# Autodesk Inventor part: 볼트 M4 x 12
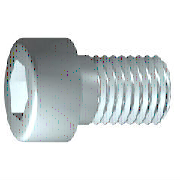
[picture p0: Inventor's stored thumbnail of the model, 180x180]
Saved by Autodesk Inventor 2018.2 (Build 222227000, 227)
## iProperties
IsCustomPart: 0
Created: 2012-02
Part Number: 볼트 M4 x 12
Material: 스테인리스강
Description: 6각 소켓 머리 캡 나사
Document SubType Name: Modeling
Standard: ISO 4762
Designer: mduedu
Standard Revision: Fourth edition 2004-03-01
Standards Organization: ISO
Language: ko-KR
Size Designation: M4 x 8
Categories: <MemberInstance><Categories><Category DisplayName="조임쇠" InternalName="e4da775c-781d-43d5-af7c-5136215cf5a6" Mnemonic="FSTN"><Category DisplayName="볼트" InternalN
Density: 8.08 g/cm^3
Mass: 2.2972 g
Surface Area: 3.30853 cm^2
Volume: 0.284306 cm^3
Appearance: 반광택
Author: mduedu
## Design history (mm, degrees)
sketch "스케치1"
  geometry: L1 (-1, 0)-(12, 0); L2 (12, 0)-(12, 2); L3 (12, 2)-(1.75, 2); L4 (1.75, 2)-(1.32, 2); L5 (1.32, 2)-(0, 2); L6 (0, 2)-(0, 3.5); L7 (0, 3.5)-(-4, 3.5); L8 (-4, 3.5)-(-4, 1.732); L9 (-4, 1.732)-(-2, 1.732); L10 (-2, 1.732)-(-1, 0); L11 (-7.2, 0)-(15.2, 0) reference; L12 (0, -0.7)-(0, 4.2) reference; L13 (1.75, 2)-(0, 2)
  constraints: 22 end point, 6 parallel, 2 collinear, 2 perpendicular, 1 horizontal, 1 point on line
  dimensions: "d1" = 10.25 distance from line of L3.end L2 (= GEL); "d2" = 0.42952 distance of L4.end L3.end (computed from GAL); "d3" = 4 distance between parallel lines of L8 L6 (= KOH); "d4" = 2 distance of L8.end L9.end (= INTI); "d5" = 60 deg angle of L10 L1; "d6" = 4 diameter of L3 L1 (= GD); "d7" = 4 diameter of L5 L1 (= BDM); "d8" = 3.4641 diameter of L9 L1 (= 1.1547 x SW); "d9" = 7 diameter of L7 L1 (= KOD); "d26" = 12 distance between parallel lines of L12 L2 (= NLG)
revolve "본체" sketch "스케치1" stored, may be unused: angle "d10" = 90 deg
sketch "스케치2"
  geometry: L1 (0, -4.9)-(0, 4.9) reference; L2 (-4.9, 0)-(4.9, 0) reference; L3 (1.732, 0)-(0.866, -1.5); L4 (0.866, -1.5)-(-0.866, -1.5); L5 (-0.866, -1.5)-(-1.732, 0); L6 (-1.732, 0)-(-0.866, 1.5); L7 (-0.866, 1.5)-(0.866, 1.5); L8 (0.866, 1.5)-(1.732, 0); 2 further points
  constraints: 12 end point, 1 coincident, 1 horizontal alignment, 1 point on line, 12 other
extrude "슬롯" join sketch "스케치2" stored distance "d11" = 10; taper "d12" = 0 deg
workplane "Work Plane1"
fillet "Fillet2" dims "d30" = 0.1 (= R)
body "Solid1"
fillet "모깎기1" dims "d17" = 0.4 (= RR)
feature "스레드" dims "d13" = 10.25 (= GEL), "d14" = 0
chamfer "모따기1" distance "d15" = 0.42941 (= -0.5 x SPD + 0.5 x GD); stored, may be unused: second distance "d16" = 0.42941 (= GUL), angle "d27" = 45 deg
other parameters: "GD" = 4 [user parameter; used in 2 equation terms], "NLG" = 12 [user parameter; used in 1 equation term], "GEL" = 10.25 [user parameter; used in 2 equation terms], "KOD" = 7 [user parameter; used in 1 equation term], "KOH" = 4 [user parameter; used in 1 equation term], "INTI" = 2 [user parameter; used in 1 equation term], "GAL" = 0.42941 (= 0.61345 x PTC) [user parameter; used in 1 equation term], "GUL" = 0.42941 (= 0.61345 x PTC) [user parameter; used in 1 equation term], "BDM" = 4 (= NND) [user parameter; used in 1 equation term], "SW" = 3 [user parameter; used in 2 equation terms], "RR" = 0.4 [user parameter; used in 1 equation term], "SPD" = 3.14117 (= NND - 1.2269 x PTC) [user parameter; used in 1 equation term], "d19" = 0, "d28" = 0, "d29" = 0, "R" = 0.1 [user parameter; used in 1 equation term], "TOA" = 30 deg [user parameter], "GD1" = 3.14117 (= THREADDIA - 1.2269 x PTC) [user parameter], "THREADDIA" = 4 [user parameter; used in 1 equation term], "FAWI" = 45 deg [user parameter], "TPU" = 14.28571 (computed from PTC) [user parameter], "PTC" = 0.7 [user parameter; used in 5 equation terms], "NND" = 4 [user parameter; used in 2 equation terms], "E0" = 3.465 (= 1.155 x SW) [user parameter]
